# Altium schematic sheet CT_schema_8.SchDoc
size 274 x 160 mm
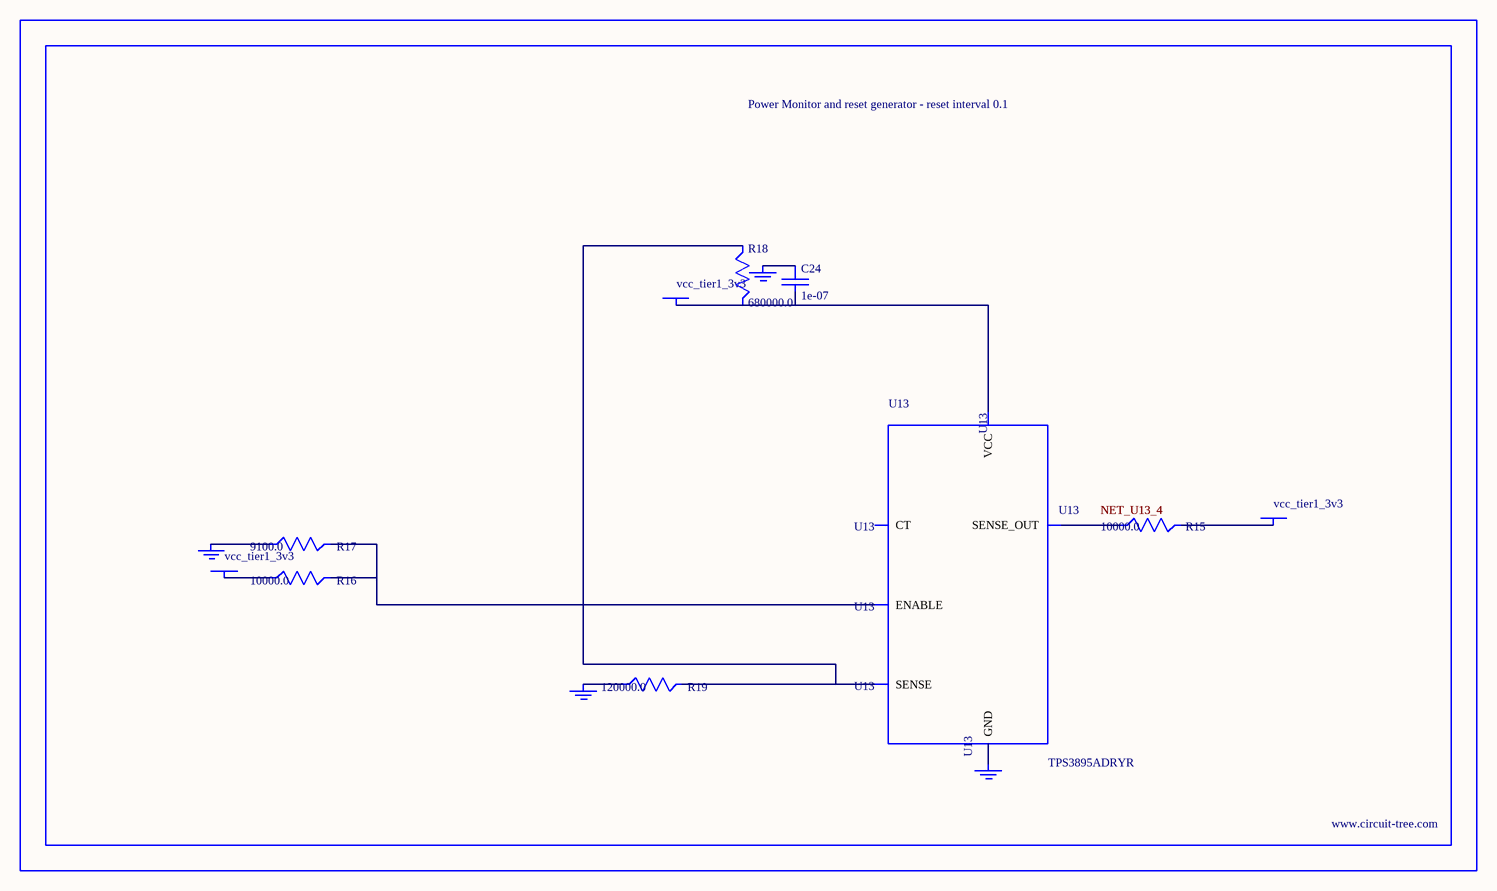
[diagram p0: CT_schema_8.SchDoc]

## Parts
BORDER7  (no value)
C24  1e-07  [C0402]
GND_INSTANCE_7_0  (no value)
GND_INSTANCE_7_1  (no value)
GND_INSTANCE_7_2  (no value)
GND_INSTANCE_7_3  (no value)
POWER_INSTANCE_7_0  vcc_tier1_3v3
POWER_INSTANCE_7_1  vcc_tier1_3v3
POWER_INSTANCE_7_2  vcc_tier1_3v3
R15  10000.0  [R0603]
R16  10000.0  [R0603]
R17  9100.0  [R0603]
R18  680000.0  [R0603]
R19  120000.0  [R0603]
U13  TPS3895ADRYR  [SON-6]

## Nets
NetC24_1: C24.1 GND_INSTANCE_7_2.0(GND)
NetC24_2: C24.2 POWER_INSTANCE_7_2.0(PWR) R18.2 U13.6(VCC)
NetGND_INSTANCE_7_0_0: GND_INSTANCE_7_0.0(GND) R17.1
NetGND_INSTANCE_7_1_0: GND_INSTANCE_7_1.0(GND) R19.1
NetGND_INSTANCE_7_3_0: GND_INSTANCE_7_3.0(GND) U13.2(GND)
NetPOWER_INSTANCE_7_0_0: POWER_INSTANCE_7_0.0(PWR) R16.1
NetPOWER_INSTANCE_7_1_0: POWER_INSTANCE_7_1.0(PWR) R15.2
NetR15_1: R15.1 U13.4(SENSE_OUT)
NetR16_2: R16.2 R17.2 U13.1(ENABLE)
NetR18_1: R18.1 R19.2 U13.3(SENSE)

Not connected (* = marked no-connect by the designer): U13 5(CT)

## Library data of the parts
BORDER7 = BORDER_PAGE7
C24 = C0402C104K3RACTU
GND_INSTANCE_7_0-GND_INSTANCE_7_3 = GND
POWER_INSTANCE_7_0-POWER_INSTANCE_7_2 = PWR
R15 R16 = RC0603JR-0710KL
R17 = RC0603JR-079K1L
R18 = RC0603JR-07680KL
R19 = RC0603JR-07120KL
